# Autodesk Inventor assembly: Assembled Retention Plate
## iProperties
Shininess: 64.0
Length Units: 11272
Angle Units: 11279
Time Units: 11290
Mass Units: 11286
Length Display Precision: 3
Angle Display Precision: 2
Compacted: True
Part Number: Assembled Retention Plate
Document SubType Name: Assembly
Created: 2003-10
Designer: jpittman
Manufacturer: Standard
Standards Organization: Custom
Density: 0.0
Volumn: 0.0
Area: 0.0
PropertySet Name: Model Information
Control State: 0
Master: False
Checked Out: False
Author: jpittman
